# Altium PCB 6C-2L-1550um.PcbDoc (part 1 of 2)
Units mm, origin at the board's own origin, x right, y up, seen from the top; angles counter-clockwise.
Board outline 120.5 x 75.92 mm, 2 copper layers (Top Layer, Bottom Layer), stack 1.586 mm thick; 122 components, 111 nets, 420 pads, 133 vias.
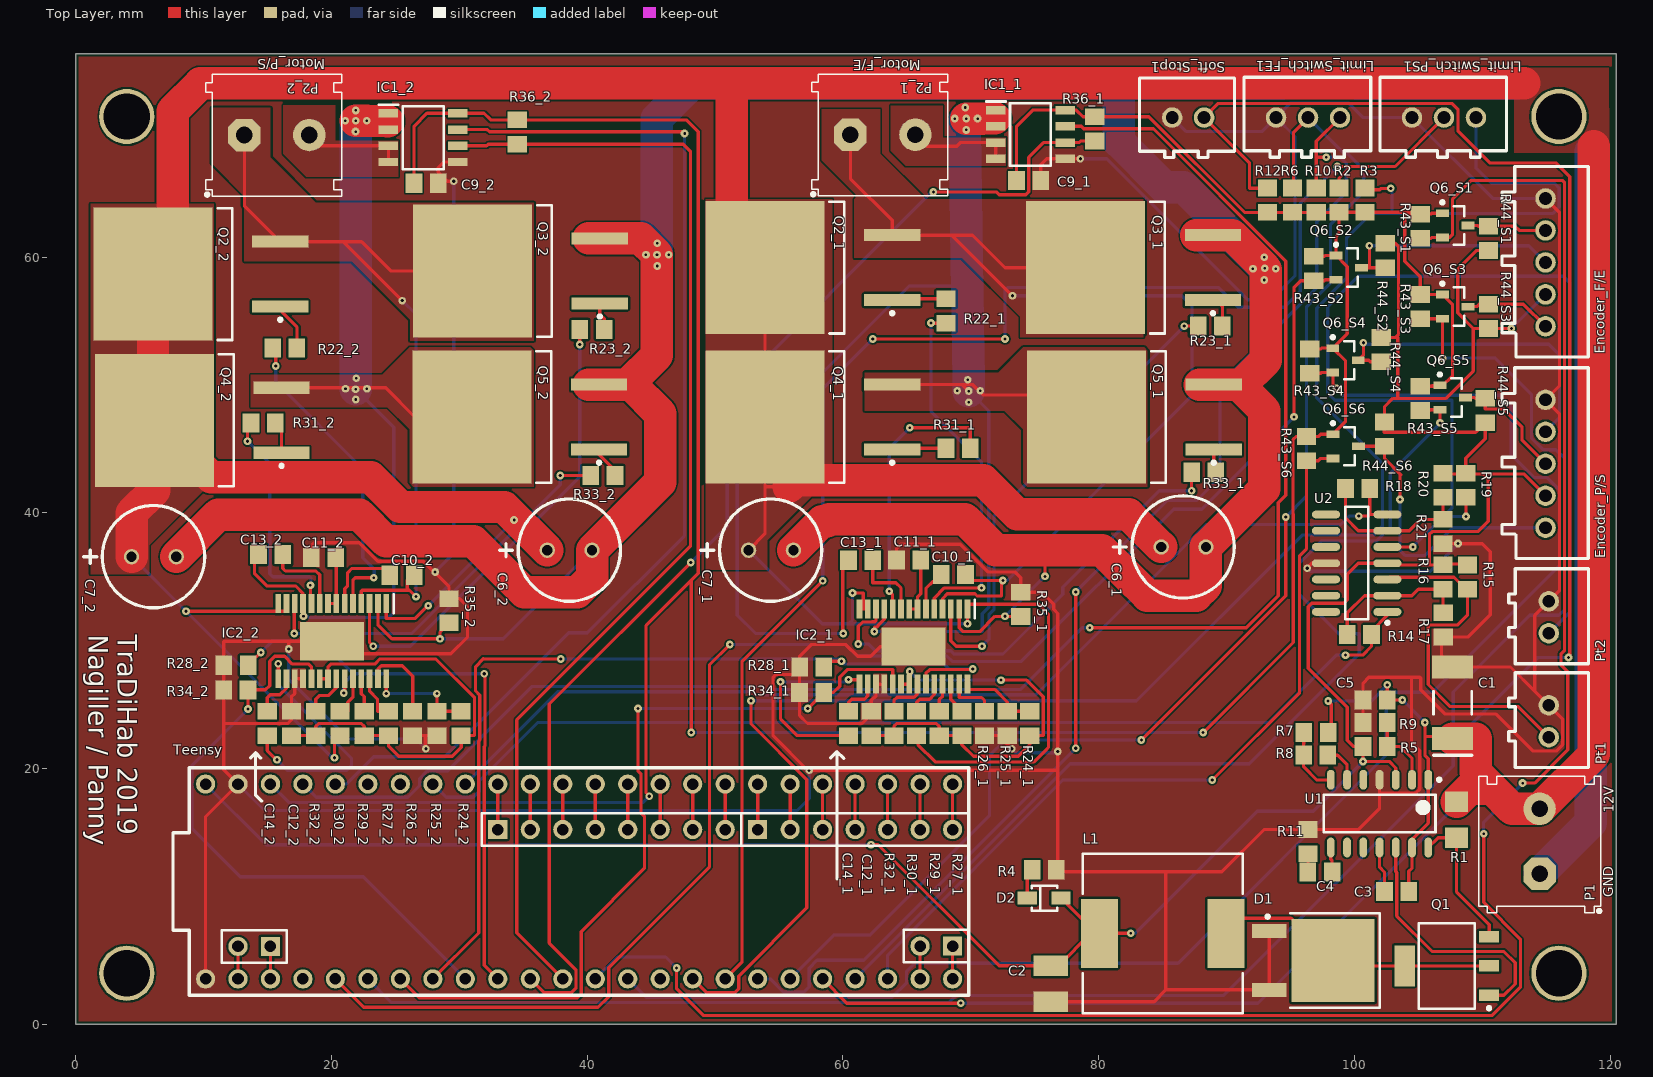
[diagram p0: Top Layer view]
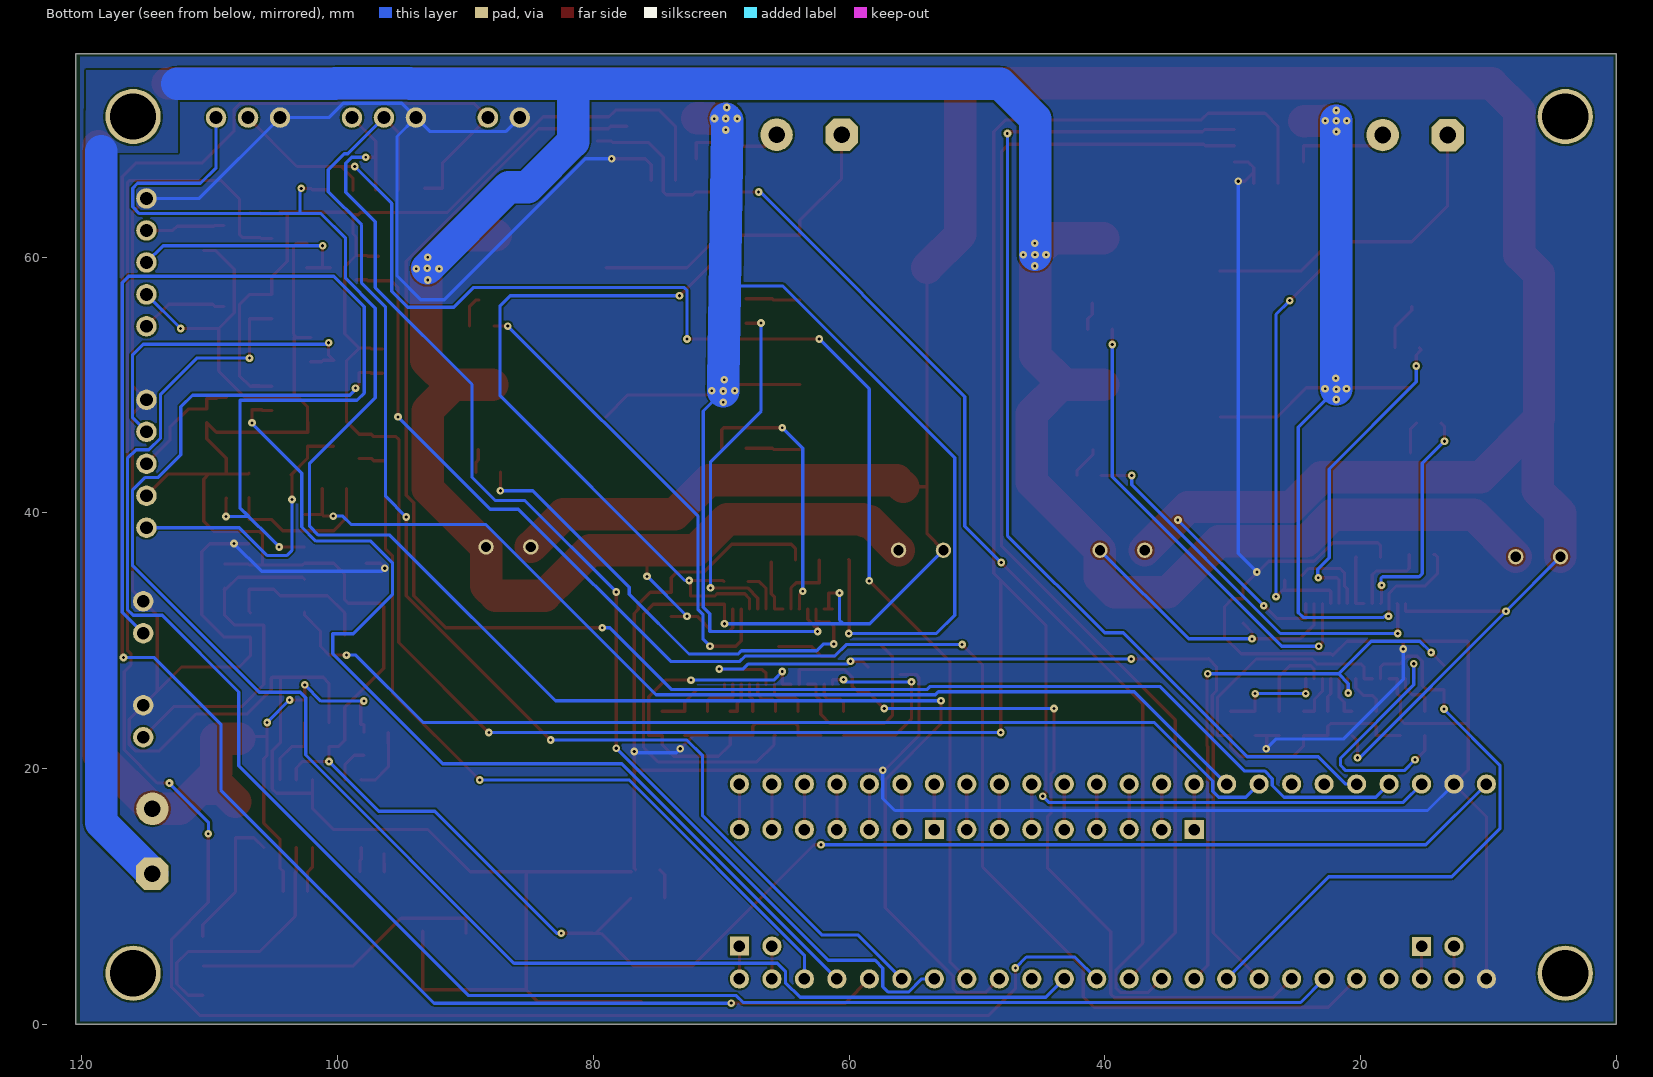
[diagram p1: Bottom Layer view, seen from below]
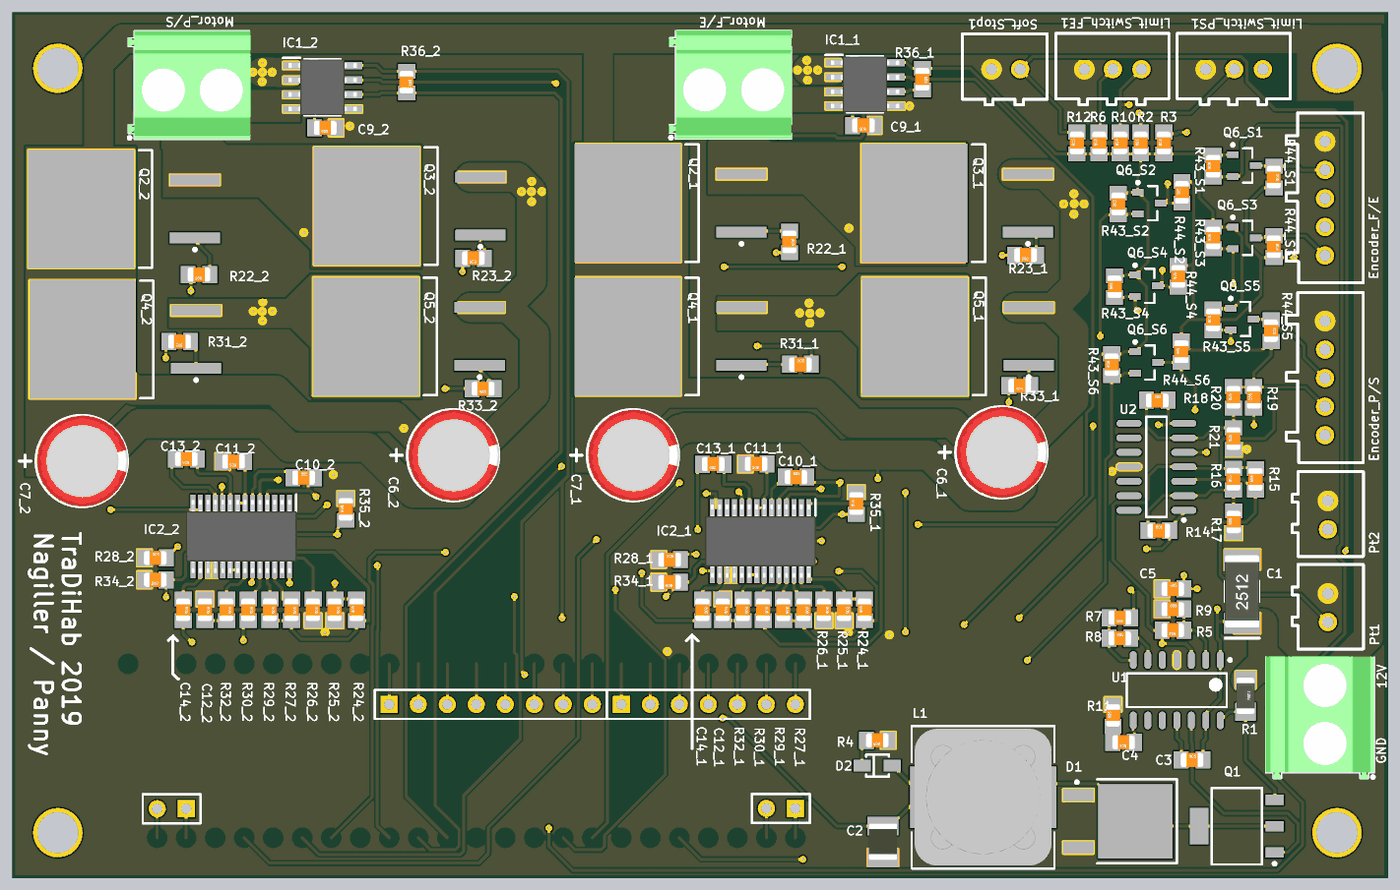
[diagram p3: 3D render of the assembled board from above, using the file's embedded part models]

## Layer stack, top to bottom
Top Solder: solder mask 0.0102, Solder Resist, Dk 3.5
Top Layer: signal copper 0.018
Dielectric1: core 1.55, FR-4, Dk 4.8
Bottom Layer: signal copper 0.018
Bottom Solder: solder mask 0.0102, Solder Resist, Dk 3.5

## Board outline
0,0 120.498,0 120.498,75.921 0,75.921

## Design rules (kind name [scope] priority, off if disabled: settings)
Clearance [All] p1: gap=0.152 ignorepadtopadclearanceinfootprint=FALSE
PolygonConnect PolygonConnect_4 [All vs IsNamedPolygon('Top Layer-No Net') Or  IsNamedPolygon('Top Layer-No Net') Or  IsNamedPolygon('Top Layer-No Net') Or  IsNamedPolygon('Top Layer-No Net') Or  IsNamedPolygon('Top Layer-No Net') Or  IsNamedPolygon('Top Layer-No Net 1') Or  IsNamedPolygon('Top Layer-No Net') Or  IsNamedPolygon('Top Layer-No Net 1') Or  IsNamedPolygon('Top Layer-No Net 1') Or  IsNamedPolygon('Top Layer-No Net 1')] p1: connectstyle=Direct reliefconductorwidth=0.254 reliefentries=4 polygonreliefangle="90 Angle" airgapwidth=0.254
PolygonConnect PolygonConnect_3 [All vs IsNamedPolygon('Top Layer-No Net 1')] p2: connectstyle=Direct reliefconductorwidth=0.254 reliefentries=4 polygonreliefangle="90 Angle" airgapwidth=0.254
PolygonConnect PolygonConnect_2 [All vs IsNamedPolygon('Top Layer-No Net 1')] p3: connectstyle=Direct reliefconductorwidth=0.254 reliefentries=4 polygonreliefangle="90 Angle" airgapwidth=0.254
PolygonConnect PolygonConnect_1 [All vs IsNamedPolygon('Top Layer-No Net 1')] p4: connectstyle=Direct reliefconductorwidth=0.254 reliefentries=4 polygonreliefangle="90 Angle" airgapwidth=0.254
PolygonConnect [All] p5: connectstyle=Direct reliefconductorwidth=0.254 reliefentries=4 polygonreliefangle="90 Angle" airgapwidth=0.254
RoutingVias [All] p1: holewidth=0.25 width=0.6 viastyle="Through Hole" minholewidth=0.2 minwidth=0.25 maxholewidth=0.1 maxwidth=2
SolderMaskExpansion [All] p1: expansion=0.102
Width [All] p1: maxlimit=2.54 minlimit=0.254 preferedwidth=0.254
30 further rules are at their usual default settings.

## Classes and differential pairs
component class 1: C6_1 C7_1 C9_1 C10_1 C11_1 C12_1 C13_1 C14_1 IC1_1 P2_1 Q2_1 Q3_1 Q4_1 Q5_1 R22_1 R23_1 R24_1 R25_1 R26_1 R27_1 R28_1 R29_1 R30_1 R31_1 R32_1 R33_1 R34_1 R35_1 R36_1
component class 2: C6_2 C7_2 C9_2 C10_2 C11_2 C12_2 C13_2 C14_2 IC1_2 IC2_2 P2_2 Q2_2 Q3_2 Q5_2 R22_2 R23_2 R24_2 R25_2 R26_2 R27_2 R28_2 R29_2 R30_2 R31_2 R32_2 R33_2 R34_2 R35_2 R36_2
component class PCB_TraDiHab: C1 C2 C3 C4 C5 D1 D2 Encoder_F/E Encoder_P/S L1 Limit_Switch_FE1 Limit_Switch_PS1 P1 Pt1 Pt2 Q1 R1 R2 R3 R4 R5 R6 R7 R8 R9 R10 R11 R12 R14 R15 R16 R17 R18 R19 R20 R21 Soft_Stop1 Teensy U1 U2
channel class motor: 1 2
component class S1: Q6_S1 R43_S1 R44_S1
component class S2: Q6_S2 R43_S2 R44_S2
component class S3: Q6_S3 R43_S3 R44_S3
component class S4: Q6_S4 R43_S4 R44_S4
component class S5: Q6_S5 R43_S5 R44_S5
component class S6: Q6_S6 R43_S6 R44_S6
channel class Level_shift: S1 S2 S3 S4 S5 S6

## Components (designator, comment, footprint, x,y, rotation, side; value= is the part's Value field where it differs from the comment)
C1 "100µF/25V Tan" C 107.696,25.152 r90 top
C2 "100µF/16V" _1210 76.248,3.178 r90 top
C3 "220nF" _0805 103.312,10.39 r0 top
C4 "22nF" _0805 97.316,11.914 r180 top
C5 "220nF" _0805 101.634,25.376 r0 top
C6_1 "100µF" Cap_THT_Elko_rad_D8mm 86.614,37.338 r0 top (schematic designator C6)
C6_2 "100µF" Cap_THT_Elko_rad_D8mm 38.608,37.084 r0 top (schematic designator C6)
C7_1 "100µF" Cap_THT_Elko_rad_D8mm 54.352,37.084 r0 top (schematic designator C7)
C7_2 "100µF" Cap_THT_Elko_rad_D8mm 6.092,36.576 r0 top (schematic designator C7)
C9_1 "100nF" _0805 74.535,65.989 r180 top (schematic designator C9)
C9_2 "100nF" _0805 27.418,65.786 r180 top (schematic designator C9)
C10_1 "100nF" _0805 68.641,35.179 r0 top (schematic designator C10)
C10_2 "100nF" _0805 25.527,35.128 r0 top (schematic designator C10)
C11_1 "4,7µF" _0805 65.151,36.322 r180 top (schematic designator C11)
C11_2 "4,7µF" _0805 19.39,36.525 r180 top (schematic designator C11)
C12_1 "1µF" _0805 62.224,23.534 r270 top (schematic designator C12)
C12_2 "1µF" _0805 16.881,23.536 r270 top (schematic designator C12)
C13_1 "100nF" _0805 61.392,36.297 r180 top (schematic designator C13)
C13_2 "100nF" _0805 15.255,36.754 r180 top (schematic designator C13)
C14_1 "470nF" _0805 60.452,23.534 r270 top (schematic designator C14)
C14_2 "470nF" _0805 14.986,23.536 r270 top (schematic designator C14)
D1 "IDD03SG60C" TO_252 95,5 r0 top
D2 "yellow" LED_SMD 75.768,9.881 r0 top
Encoder_F/E "JST_5_top" JST_5_TOP 112.456,64.592 r0 top
Encoder_P/S "JST_5_top" JST_5_TOP 112.456,48.844 r0 top
IC1_1 "ACS71240LLCBTR-030B3" SOIC127P600X175-8N 74.676,69.596 r0 top (schematic designator IC1)
IC1_2 "ACS71240LLCBTR-030B3" SOIC127P600X175-8N 27.178,69.342 r0 top (schematic designator IC1)
IC2_1 "A3941KLPTR" SOP65P640X120-29N 65.523,29.549 r270 top (schematic designator IC2)
IC2_2 "A3941KLPTR" SOP65P640X120-29N 20.066,29.972 r270 top (schematic designator IC2)
L1 "IND_47u_3A8" WE_PD_XXL 85.014,7.112 r180 top
Limit_Switch_FE1 "JST_3_top" JST_3_TOP 93.884,74.417 r90 top
Limit_Switch_PS1 "JST_3_top" JST_3_TOP 104.512,74.417 r90 top
P1 "Power_Supply" WRTBL_2P_508 114.702,14.332 r90 top
P2_1 "WRTBL_2P_508" WRTBL_2P_508 63.144,69.367 r0 top (schematic designator P2)
P2_2 "WRTBL_2P_508" WRTBL_2P_508 15.748,69.342 r0 top (schematic designator P2)
P3 "Header 8" HDR1X8 33.02,15.24 r0 top
P4 "Header 7" HDR1X7 53.34,15.24 r0 top
P5 "Header 2" HDR1X2 15.24,6.096 r180 top
P6 "Header 2" HDR1X2 68.58,6.121 r180 top
Pt1 "JST_2_top" JST_2_TOP 120.21,24.96 r0 top
Pt2 "JST_2_top" JST_2_TOP 120.21,33.088 r0 top
Q1 "BSP613P" INF-PG-SOT223_SC-73_N 107.234,4.572 r180 top
Q2_1 "IPB034N06L3 G" INF-PG-TO-263-3-2_A_N 57.658,59.182 r180 top (schematic designator Q2)
Q2_2 "IPB034N06L3 G" INF-PG-TO-263-3-2_A_N 9.802,58.674 r180 top (schematic designator Q2)
Q3_1 "IPB034N06L3 G" INF-PG-TO-263-3-2_A_N 82.744,59.182 r180 top (schematic designator Q3)
Q3_2 "IPB034N06L3 G" INF-PG-TO-263-3-2_A_N 34.798,58.928 r180 top (schematic designator Q3)
Q4_1 "IPB034N06L3 G" INF-PG-TO-263-3-2_A_N 57.658,47.498 r180 top (schematic designator Q4)
Q4_2 "IPB034N06L3 G" INF-PG-TO-263-3-2_A_N 9.906,47.244 r180 top (schematic designator Q4)
Q5_1 "IPB034N06L3 G" INF-PG-TO-263-3-2_A_N 82.804,47.498 r180 top (schematic designator Q5)
Q5_2 "IPB034N06L3 G" INF-PG-TO-263-3-2_A_N 34.738,47.498 r180 top (schematic designator Q5)
Q6_S1 "BSS138" SOT_23 107.888,62.484 r0 top (schematic designator Q6)
Q6_S2 "BSS138" SOT_23 99.568,59.182 r0 top (schematic designator Q6)
Q6_S3 "BSS138" SOT_23 107.888,56.134 r0 top (schematic designator Q6)
Q6_S4 "BSS138" SOT_23 99.314,51.938 r0 top (schematic designator Q6)
Q6_S5 "BSS138" SOT_23 107.696,49.022 r0 top (schematic designator Q6)
Q6_S6 "BSS138" SOT_23 99.33,45.212 r0 top (schematic designator Q6)
R1 "0,047R" _1206 108,16 r270 top
R2 "10k" _0805 98.806,64.465 r90 top
R3 "10k" _0805 100.838,64.465 r90 top
R4 "470R" _0805 75.753,12.09 r180 top
R5 "" _0805 101.634,21.742 r180 top
R6 "10k" _0805 95.174,64.465 r90 top
R7 "" _0805 97.003,22.835 r180 top
R8 "" _0805 96.984,21.058 r0 top
R9 "" _0805 101.634,23.598 r0 top
R10 "10k" _0805 97.028,64.465 r90 top
R11 "430R" _0805 96.388,14.288 r90 top
R12 "10k" _0805 93.218,64.465 r90 top
R14 "6.8k" _0805 100.396,30.48 r0 top
R15 "4.7k" _0805 108.864,34.976 r90 top
R16 "4.7k" _0805 106.934,34.986 r90 top
R17 "100" _0805 106.959,31.242 r90 top
R18 "6.8k" _0805 100.264,41.91 r0 top
R19 "4.7k" _0805 108.712,42.164 r90 top
R20 "4.7k" _0805 106.934,42.164 r90 top
R21 "100" _0805 106.934,38.542 r90 top
R22_1 "47R5" _0805 68.072,55.792 r270 top (schematic designator R22)
R22_2 "47R5" _0805 16.358,52.908 r180 top (schematic designator R22)
R23_1 "47R5" _0805 88.734,54.61 r180 top (schematic designator R23)
R23_2 "47R5" _0805 40.386,54.356 r180 top (schematic designator R23)
R24_1 "47k" _0805 74.625,23.534 r90 top (schematic designator R24)
R24_2 "47k" _0805 30.15,23.536 r90 top (schematic designator R24)
R25_1 "4k7" _0805 72.854,23.534 r270 top (schematic designator R25)
R25_2 "4k7" _0805 28.254,23.536 r270 top (schematic designator R25)
R26_1 "47k" _0805 71.082,23.534 r270 top (schematic designator R26)
R26_2 "47k" _0805 26.359,23.536 r270 top (schematic designator R26)
R27_1 "47k" _0805 69.31,23.534 r270 top (schematic designator R27)
R27_2 "47k" _0805 24.463,23.536 r270 top (schematic designator R27)
R28_1 "47k" _0805 57.57,27.94 r0 top (schematic designator R28)
R28_2 "47k" _0805 12.537,28.092 r0 top (schematic designator R28)
R29_1 "47k" _0805 67.539,23.534 r270 top (schematic designator R29)
R29_2 "47k" _0805 22.568,23.536 r270 top (schematic designator R29)
R30_1 "20k" _0805 65.767,23.534 r270 top (schematic designator R30)
R30_2 "20k" _0805 20.672,23.536 r270 top (schematic designator R30)
R31_1 "47R5" _0805 69.022,45.058 r0 top (schematic designator R31)
R31_2 "47R5" _0805 14.671,47.041 r180 top (schematic designator R31)
R32_1 "47k" _0805 63.995,23.534 r270 top (schematic designator R32)
R32_2 "47k" _0805 18.777,23.536 r270 top (schematic designator R32)
R33_1 "47R5" _0805 88.226,43.18 r180 top (schematic designator R33)
R33_2 "47R5" _0805 41.236,42.926 r180 top (schematic designator R33)
R34_1 "47k" _0805 57.567,25.959 r180 top (schematic designator R34)
R34_2 "47k" _0805 12.534,26.162 r180 top (schematic designator R34)
R35_1 "0R" _0805 73.914,32.854 r90 top (schematic designator R35)
R35_2 "0R" _0805 29.21,32.346 r90 top (schematic designator R35)
R36_1 "" _0805 79.705,70.038 r270 top (schematic designator R36)
R36_2 "" _0805 34.544,69.784 r270 top (schematic designator R36)
R43_S1 "10k" _0805 105.156,62.418 r90 top (schematic designator R43)
R43_S2 "10k" _0805 96.836,59.116 r90 top (schematic designator R43)
R43_S3 "10k" _0805 105.156,56.134 r90 top (schematic designator R43)
R43_S4 "10k" _0805 96.52,51.872 r90 top (schematic designator R43)
R43_S5 "10k" _0805 105.156,48.956 r90 top (schematic designator R43)
R43_S6 "10k" _0805 96.266,45.024 r90 top (schematic designator R43)
R44_S1 "10k" _0805 110.49,61.468 r270 top (schematic designator R44)
R44_S2 "10k" _0805 102.424,60.132 r90 top (schematic designator R44)
R44_S3 "10k" _0805 110.49,55.372 r270 top (schematic designator R44)
R44_S4 "10k" _0805 102.108,52.766 r90 top (schematic designator R44)
R44_S5 "10k" _0805 110.236,48.006 r270 top (schematic designator R44)
R44_S6 "10k" _0805 102.362,46.162 r90 top (schematic designator R44)
Soft_Stop1 "JST_2_top" JST_2_TOP 85.756,75.917 r90 top
Teensy "Teensy3.6_TraDiHab" TEENSY3_6FOOTPRINT 170.18,168.656 r90 top
U1 "IFX80471SK V" INF-PG-DSO-14-1_N 101.976,16.486 r270 top
U2 "LM324" SO_14 100.19,36.068 r180 top

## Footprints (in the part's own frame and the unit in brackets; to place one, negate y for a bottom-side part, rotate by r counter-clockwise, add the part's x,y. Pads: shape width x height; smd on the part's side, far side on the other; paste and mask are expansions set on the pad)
_0805 [mm]
  rect 1.3x1.5 smd: 1(-0.95,0) 2(0.95,0)
  body extent -1,-0.64 1,0.62, height 0.78
_1206 [mm]
  rect 1.6x1.8 smd: 1(-1.4,0) 2(1.4,0)
  body extent -1.6,-0.81 1.6,0.79, height 1
_1210 [mm]
  rect 1.6x2.7 smd: 1(-1.4,0) 2(1.4,0)
  body extent -1.57,-1.24 1.63,1.26, height 1.5
C [mm]
  rect 1.8x3.2 smd: 1(-2.8,0) 2(2.8,0)
  silkscreen extent -4.1,-1.5 0.9,1.5, body extent -3.17,-1.5 3.17,1.5, height 1.6
Cap_THT_Elko_rad_D8mm [mm]
  round 1.2 hole 0.8: 1(-1.718,0) 2(1.782,0)
  silkscreen extent -5.46,-4 4,4, body extent -3.94,-4 4.06,4, height 11.74
HDR1X2 [mm] "Connector; Header; 2 Position"
  rect 1.5x1.5 hole 0.9: 1(0,0)
  round 1.5 hole 0.9: 2(2.54,0)
  silkscreen extent -1.27,-1.27 3.81,1.27, body extent -0.3,-0.29 2.84,0.3, height 7
HDR1X7 [mm] "Connector; Header; 7 Position"
  rect 1.5x1.5 hole 0.9: 1(0,0)
  round 1.5 hole 0.9: 2(2.54,0) 3(5.08,0) 4(7.62,0) 5(10.16,0) 6(12.7,0) 7(15.24,0)
  silkscreen extent -1.27,-1.27 16.51,1.27, body extent -0.3,-0.29 15.54,0.33, height 7
HDR1X8 [mm] "Connector; Header; 8 Position"
  rect 1.5x1.5 hole 0.9: 1(0,0)
  round 1.5 hole 0.9: 2(2.54,0) 3(5.08,0) 4(7.62,0) 5(10.16,0) 6(12.7,0) 7(15.24,0) 8(17.78,0)
  silkscreen extent -1.27,-1.27 19.05,1.27, body extent -0.3,-0.29 18.08,0.3, height 7
INF-PG-DSO-14-1_N [mm]
  oval 1.55x0.6 smd: 1(-2.65,3.81) 2(-2.65,2.54) 3(-2.65,1.27) 4(-2.65,0) 5(-2.65,-1.27) 6(-2.65,-2.54) 7(-2.65,-3.81) 8(2.65,-3.81) 9(2.65,-2.54) 10(2.65,-1.27) 11(2.65,0) 12(2.65,1.27) 13(2.65,2.54) 14(2.65,3.81)
  silkscreen extent -2.77,-4.38 1.47,4.79, body extent -2,-4.38 2,4.38, height 1.75
INF-PG-SOT223_SC-73_N [mm]
  rect 1.6x0.9 smd: 1(-3.3,2.3) 2(-3.3,0) 3(-3.3,-2.3)
  rect 1.6x3.2 smd: 4(3.3,0)
  silkscreen extent -3.43,-3.35 2.2,3.42, body extent -1.85,-3.35 1.85,3.35, height 1.8
INF-PG-TO-263-3-2_A_N [mm]
  rect 4.4x0.95 smd: 1(-6.2,2.54) 3(-6.2,-2.54)
  rect 9.3x10.4 smd: 2(3.75,0)
  silkscreen extent -6.33,-5.15 -1.3,5.15, body extent -2.45,-5.15 7,5.15, height 4.57
JST_2_TOP [mm]
  round 1.6 hole 1: 1(-5,0) 2(-5,-2.5)
  silkscreen extent -8.13,-4.87 -1.9,2.55, body extent -8.25,-5 -1.77,2.68, height 7
JST_3_TOP [mm]
  round 1.6 hole 1: 1(-3.5,0) 2(-3.5,-2.5) 3(-3.5,-5)
  silkscreen extent -6.6,-7.4 -0.35,2.5, body extent -6.73,-7.53 -0.22,2.63, height 7
JST_5_TOP [mm]
  round 1.6 hole 1: 1(2.5,0) 2(2.5,-2.5) 3(2.5,-5) 4(2.5,-7.5) 5(2.5,-10)
  silkscreen extent -0.9,-12.4 5.85,2.5, body extent -1.03,-12.53 5.98,2.63, height 7
LED_SMD [mm]
  rect 1.5x1 smd: 1(1.298,0) 2(-1.349,0)
  silkscreen extent -1,-0.98 1,0.98, body extent -1.12,-0.85 1.23,0.85, height 1.3
SO_14 [mm]
  oval 2.2x0.6 smd: 1(-2.4,3.81) 2(-2.4,2.54) 3(-2.4,1.27) 4(-2.4,0) 5(-2.4,-1.27) 6(-2.4,-2.54) 7(-2.4,-3.81) 8(2.4,-3.81) 9(2.4,-2.54) 10(2.4,-1.27) 11(2.4,0) 12(2.4,1.27) 13(2.4,2.54) 14(2.4,3.81)
  silkscreen extent -2.53,-4.4 0.9,4.78, body extent -2,-4.38 2,4.38, height 1.75
SOIC127P600X175-8N [mm]
  rect 1.525x0.65 smd: 1(-2.712,1.905) 2(-2.712,0.635) 3(-2.712,-0.635) 4(-2.712,-1.905) 5(2.712,-1.905) 6(2.712,-0.635) 7(2.712,0.635) 8(2.712,1.905)
  silkscreen extent -3.48,-2.45 1.6,2.58, body extent -3,-2.45 3,2.45, height 1.75
SOP65P640X120-29N [mm]
  rect 1.475x0.45 smd: 1(-2.938,4.225) 2(-2.938,3.575) 3(-2.938,2.925) 4(-2.938,2.275) 5(-2.938,1.625) 6(-2.938,0.975) 7(-2.938,0.325) 8(-2.938,-0.325) 9(-2.938,-0.975) 10(-2.938,-1.625) 11(-2.938,-2.275) 12(-2.938,-2.925) 13(-2.938,-3.575) 14(-2.938,-4.225) 15(2.938,-4.225) 16(2.938,-3.575) 17(2.938,-2.925) 18(2.938,-2.275) 19(2.938,-1.625) 20(2.938,-0.975) 21(2.938,-0.325) 22(2.938,0.325) 23(2.938,0.975) 24(2.938,1.625) 25(2.938,2.275) 26(2.938,2.925) 27(2.938,3.575) 28(2.938,4.225)
  rect 3x5 smd: 29(0,0)
  silkscreen extent -3.68,4.8 -2.2,4.8, body extent -3.2,-4.85 3.2,4.85, height 1.2
SOT_23 [mm]
  rect 1x0.6 smd: 1(-1,0.95) 2(-1,-0.95) 3(1,0)
  silkscreen extent -1.12,-1.5 0.7,1.92, body extent -0.7,-1.5 0.7,1.5, height 1.1
TEENSY3_6FOOTPRINT [mm]
  round 1.5 hole 0.9: 1(-165.1,160.02) 2(-165.1,157.48) 3(-165.1,154.94) 4(-165.1,152.4) 5(-165.1,149.86) 6(-165.1,147.32) 7(-165.1,144.78) 8(-165.1,142.24) 9(-165.1,139.7) 10(-165.1,137.16) 11(-165.1,134.62) 12(-165.1,132.08) 13(-165.1,129.54) 14(-165.1,127) 15(-165.1,124.46) 16(-165.1,121.92) 17(-165.1,119.38) 18(-165.1,116.84) 19(-165.1,114.3) 20(-165.1,111.76) 21(-165.1,109.22) 22(-165.1,106.68) 23(-165.1,104.14) 24(-165.1,101.6) 25(-149.86,160.02) 26(-149.86,157.48) 27(-149.86,154.94) 28(-149.86,152.4) 29(-149.86,149.86) 30(-149.86,147.32) 31(-149.86,144.78) 32(-149.86,142.24) 33(-149.86,139.7) 34(-149.86,137.16) 35(-149.86,134.62) 36(-149.86,132.08) 37(-149.86,129.54) 38(-149.86,127) 39(-149.86,124.46) 40(-149.86,121.92) 41(-149.86,119.38) 42(-149.86,116.84) 43(-149.86,114.3) 44(-149.86,111.76) 45(-149.86,109.22) 46(-149.86,106.68) 47(-149.86,104.14) 48(-149.86,101.6)
  silkscreen extent -166.37,100.33 -148.59,162.56, body extent -166.5,100.2 -148.46,162.69, height 14
TO_252 [mm]
  rect 2.7x1.1 smd: 1(-1.643,2.3) 2(-1.643,-2.3)
  rect 6.5x6.5 smd: 3(3.346,0)
  silkscreen extent -1.9,-3.68 6.99,3.68, body extent 0,-3.43 6.73,3.43, height 2.3
WE_PD_XXL [mm]
  rect 2.9x5.4 smd: 1(-4.95,0) 2(4.95,0)
  silkscreen extent -6.25,-6.25 6.25,6.25, body extent -6,-6 6,6, height 10.36
WRTBL_2P_508 [mm]
  oct 2.54x2.54 hole 1.3: 1(-2.549,0.212)
  round 2.54 hole 1.3: 2(2.531,0.212)
  silkscreen extent -5.59,-4.57 5.08,4.95, body extent -5.62,-4.55 5.11,4.95, height 15

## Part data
C1: library part Cap_56, Capacity=47u, Voltage=25v
C2: library part Cap_65, Capacity=?F, Voltage=?V
C3 C5: library part Cap_63, Capacity=?F, Voltage=?V
C4 C9_1 C9_2 C10_1 C10_2 C11_1 C11_2 C13_1 C13_2 C14_1 C14_2: library part Cap_129
C6_1 C6_2 C7_1 C7_2: library part Cap_15, Capacity=100u, Voltage=35V
C12_1 C12_2: library part Cap_128
D1: library part DIODE_12, Current / Power="3.5 A"
D2: library part DIODE_60, Colour=blau
IC1_1 IC1_2: library part ACS712ELCTR-20A-T, "Integrated Circuit", Manufacturer_Name="Allegro Microsystems", RS Part Number=6807135P
IC2_1 IC2_2: "Integrated Circuit", Manufacturer_Name="Allegro Microsystems", RS Part Number=7248704P
L1: library part Ind_8, "Inductor", Current="3.8 A", Inductivity="47 uH"
P1 P2_1 P2_2: library part Con_7
P3: library part Con_38
P4: library part Con_37
P5 P6: library part Con_32
Q1: library part Tran_33, "P-Channel SIPMOS Small-Signal-Transistor, -60 V VDS, -2.9 A ID, -55 to 150 degC, PG-SOT223 (SC-73), Reel, Green", Manufacturer=Infineon, Supplier Part Number 1=BSP613P-ND
Q2_1 Q2_2 Q3_1 Q3_2 Q4_1 Q4_2 Q5_1 Q5_2: "N-Channel OptiMOS 3 Power-Transistor, 60 V VDS, 90 A ID, -55 to 175 degC, PG-TO-263-3-2, Reel, Green", Manufacturer=Infineon, Supplier Part Number 1="IPB034N06L3 GTR-ND"
Q6_S1 Q6_S2 Q6_S3 Q6_S4 Q6_S5 Q6_S6: library part Tran_11, Current="2.2 A"
R1: library part Res_7
R2 R3 R6 R10 R12 R14 R15 R16 R17 R18 R19 R20 R21 R36_1 R36_2 R43_S1 R43_S2 R43_S3 R43_S4 R43_S5 R43_S6 R44_S1 R44_S2 R44_S3 R44_S4 R44_S5 R44_S6: library part Res_6
R4 R5 R7 R8 R9 R11 R22_1 R22_2 R23_1 R23_2 R24_1 R24_2 R25_1 R25_2 R26_1 R26_2 R27_1 R27_2 R28_1 R28_2 R29_1 R29_2 R30_1 R30_2 R31_1 R31_2 R32_1 R32_2 R33_1 R33_2 R34_1 R34_2 R35_1 R35_2: library part Res_5
U1: "Step-Down DC/DC Controller, 2,300 mA Iq, -40 to 125 degC, PG-DSO-14-1, Reel, Green", Manufacturer=Infineon, Max Peak Reflow Temp="260 degC", Supplier Part Number 1="IFX80471SK VINTR-ND", Tolerance=3(5)%
U2: library part IC_46

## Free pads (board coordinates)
  round 4.318 hole 3.599: 6(4,4) 6(4,71) 6(116,4) 6(116,71)

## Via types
v1: diameter 0.6, hole 0.25, Top Layer to Bottom Layer, 89 vias
v2: diameter 0.6, hole 0.2, Top Layer to Bottom Layer, 44 vias

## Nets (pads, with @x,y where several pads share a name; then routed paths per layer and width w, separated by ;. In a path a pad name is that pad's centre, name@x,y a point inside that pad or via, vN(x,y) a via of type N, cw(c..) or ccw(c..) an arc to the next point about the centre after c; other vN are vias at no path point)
3V3: C9_1.2 C9_2.2 IC1_1.8 IC1_2.8 Q6_S1.1 Q6_S2.1 Q6_S3.1 Q6_S4.1 Q6_S5.1 Q6_S6.1 R2.1 R3.1 R6.1 R10.1 R12.1 R36_1.1 R36_2.1 R43_S1.2 R43_S2.2 R43_S3.2 R43_S4.2 R43_S5.2 R43_S6.2 Teensy.27 | length 277.1
  Top Layer w0.254: C9_2.2@26.468,65.786 26.468,70.243 27.472,71.247 IC1_2.8@29.89,71.247 31.94,71.247 32.453,70.734 R36_2.1@34.544,70.734 47.757,70.734 48.687,69.804 48.687,35.276 48.145,34.734 ; v1(44.869,17.843) 44.616,18.096 44.616,31.205 48.145,34.734 ; v1(48.145,22.821) 48.145,34.734 ; C9_1.2@73.585,65.989 73.585,70.243 74.843,71.501 IC1_1.8@77.388,71.501 78.27,71.501 78.783,70.988 R36_1.1@79.705,70.988 83.924,70.988 91.412,63.5 98.191,63.5 98.379,63.312 R2.1@98.806,63.312 ; v1(88.176,22.821) 95.22,29.866 95.22,39.915 95.211,39.923 95.211,45.745 95.44,45.974 R43_S6.2@96.266,45.974 97.193,45.974 97.381,46.162 Q6_S6.1@98.33,46.162 99.321,47.153 99.321,51.881 Q6_S4.1@98.314,52.888 ; R43_S4.2@96.52,52.822 97.37,52.822 97.436,52.888 Q6_S4.1@98.314,52.888 ; R43_S2.2@96.836,60.066 97.65,60.066 97.716,60.132 Q6_S2.1@98.568,60.132 ; Q6_S5.1@106.696,49.972 106.078,49.972 R43_S5.2@105.156,49.906 106.853,49.906 107.683,50.736 107.683,56.289 Q6_S3.1@106.888,57.084 R43_S3.2@105.156,57.084 105.156,58.458 103.937,59.677 103.937,63.515 ; Q6_S1.1@106.888,63.434 106.047,63.434 105.981,63.368 R43_S1.2@105.156,63.368 104.338,63.368 104.485,63.515 103.937,63.515 ; Q6_S4.1@98.314,52.888 99.453,54.027 99.453,59.247 Q6_S2.1@98.568,60.132 ; Q6_S2.1@98.568,60.132 98.568,61.582 98.806,61.82 R2.1@98.806,63.312 ; R2.1@98.806,63.312 99.009,63.515 R3.1@100.838,63.515 103.937,63.515
  Bottom Layer w0.254: Teensy.27@15.24,18.796 16.676,17.36 44.386,17.36 v1(44.869,17.843) ; v1(48.145,22.821) v1(88.176,22.821)
5V: C2.2 D2.1 Encoder_F/E.4 Encoder_P/S.4 L1.2 R5.2 R15.2 R16.2 R19.2 R20.2 R44_S1.2 R44_S2.2 R44_S3.2 R44_S4.2 R44_S5.2 R44_S6.2 Teensy.25 U1.3 U2.4 | length 216
  Top Layer w0.254: v1(62.205,14.046) 62.751,14.046 72.219,4.578 C2.2@76.248,4.578 76.873,4.578 79.407,7.112 L1.2@80.064,7.112 ; D2.1@77.067,9.881 79.835,7.112 L1.2@80.064,7.112 ; v2(82.525,7.137) 80.089,7.137 L1.2@80.064,7.112 ; R44_S4.2@102.108,53.716 103.195,53.716 ; R44_S2.2@102.424,61.082 103.191,61.082 103.466,60.807 103.466,53.987 103.195,53.716 ; U1.3@103.246,19.136 103.246,20.053 102.733,20.565 v1(100.684,20.565) R5.2@100.684,21.742 99.91,21.742 99.44,22.213 99.44,24.816 96.405,27.851 96.405,32.677 96.659,32.931 99.174,32.931 99.479,33.235 99.479,35.23 100.317,36.068 U2.4@102.59,36.068 102.722,35.936 105.879,35.936 ; R20.2@106.934,43.114 107,43.048 R19.2@108.712,43.048 ; R15.2@108.859,36.002 107,36.002 R16.2@106.934,35.936 105.879,35.936 ; R44_S1.2@110.49,60.518 109.537,60.518 108.089,59.07 108.089,55.641 109.308,54.422 ; v1(112.286,54.422) R44_S3.2@110.49,54.422 109.308,54.422 ; Encoder_P/S.4@114.956,41.344 113.252,43.048 110.07,43.048 ; 103.195,53.716 103.403,53.716 103.403,48.958 ; 103.403,48.958 107.175,48.958 109.308,51.092 109.308,54.422 ; 103.403,48.958 103.022,48.958 102.362,48.298 R44_S6.2@102.362,47.112 102.349,47.112 102.349,46.304 109.484,46.304 R44_S5.2@110.236,47.056 110.236,45.808 108.712,44.284 R19.2@108.712,43.048 ; 105.879,35.936 105.879,38.341 106.083,38.544 109.664,38.544 110.477,39.357 110.477,42.642 110.07,43.048 ; R19.2@108.712,43.048 110.07,43.048
  Bottom Layer w0.254: Teensy.25@10.16,18.796 14.91,14.046 v1(62.205,14.046) ; v2(82.525,7.137) 82.88,7.137 92.405,16.662 96.781,16.662 v1(100.684,20.565) ; v1(112.286,54.422) Encoder_F/E.4@114.956,57.092
5V_1: C12_1.2 IC2_1.20 IC2_1.21 R24_1.1 R27_1.2 R29_1.2 R32_1.2 | length 33.2
  Top Layer w0.254: C12_1.2@62.224,22.584 R32_1.2@63.995,22.584 63.995,23.304 64.224,23.533 67.31,23.533 67.539,23.304 R29_1.2@67.539,22.584 R27_1.2@69.31,22.584 69.31,21.882 70.22,20.972 73.716,20.972 74.625,21.882 R24_1.1@74.625,22.584 75.679,22.584 75.679,25.616 74.371,26.924 v1(72.365,26.924) ; IC2_1.20@64.548,26.611 IC2_1.21@65.198,26.611 65.232,26.644 v2(65.232,27.596) v2@65.215,27.596
  Bottom Layer w0.254: v2(65.232,27.596) 65.904,26.924 v1(72.365,26.924)
5V_2: C12_2.2 IC2_2.20 IC2_2.21 R24_2.1 R27_2.2 R29_2.2 R32_2.2 | length 35.8
  Top Layer w0.254: C12_2.2@16.881,22.586 R32_2.2@18.777,22.586 18.777,23.304 19.006,23.533 22.339,23.533 22.568,23.304 R29_2.2@22.568,22.586 R27_2.2@24.463,22.586 24.463,21.789 25.28,20.972 29.456,20.972 30.15,21.666 R24_2.1@30.15,22.586 31.203,22.586 31.203,25.539 28.165,28.577 23.785,28.577 23.389,28.181 19.944,28.181 19.741,27.978 IC2_2.21@19.741,27.034 IC2_2.20@19.091,27.034
GND: C1.2 C2.1 C5.1 C9_1.1 C9_2.1 C11_1.2 C11_2.2 C12_1.1 C12_2.1 D1.1 D1.2 Encoder_F/E.1 Encoder_P/S.1 IC1_1.5 IC1_2.5 IC2_1.17 IC2_1.18 IC2_1.29 IC2_2.17 IC2_2.18 IC2_2.29 Limit_Switch_FE1.1 Limit_Switch_PS1.1 Pt1.1 Pt2.1 R4.1 R9.1 R11.2 R17.1 R21.1 R25_1.2 R25_2.2 R26_1.2 R26_2.2 R28_1.1 R28_2.1 R34_1.2 R34_2.2 R35_1.2 R35_2.2 Soft_Stop1.1 Teensy.1 Teensy.26 U1.4 U2.11 | length 527.4
  Top Layer w0.254: Teensy.1@10.16,3.556 10.16,16.256 Teensy.26@12.7,18.796 11.584,19.912 11.584,23.544 ; v1(16.662,29.362) 16.662,29.896 16.586,29.972 ; IC2_2.18@17.791,27.034 IC2_2.17@17.141,27.034 17.141,25.875 16.881,25.615 C12_2.1@16.881,24.486 16.881,23.816 16.598,23.533 11.596,23.533 11.584,23.544 ; C11_2.2@18.44,36.525 18.44,37.44 18.669,37.668 22.195,37.668 23.643,36.22 27.203,36.22 29.21,34.214 R35_2.2@29.21,33.296 30.025,33.296 30.646,32.675 30.646,30.29 29.34,28.984 22.311,28.984 22.184,28.857 21.069,29.972 IC2_2.29@20.066,29.972 16.586,29.972 ; R26_2.2@26.359,22.586 27.343,22.586 ; v1(27.393,21.551) 27.343,21.602 27.343,22.586 ; R25_2.2@28.254,22.586 27.343,22.586 ; C9_2.1@28.368,65.786 28.368,66.627 ; v1(29.566,65.938) 29.057,65.938 28.368,66.627 ; IC1_2.5@29.89,67.437 28.79,67.437 28.368,67.015 28.368,66.627 ; R28_1.1@56.019,27.368 54.749,27.368 54.546,27.165 54.546,22.567 57.238,19.875 v1(57.365,19.875) 76.746,19.875 76.81,19.939 ; IC2_1.18@63.248,26.611 IC2_1.17@62.598,26.611 62.598,25.711 62.224,25.336 C12_1.1@62.224,24.484 62.224,24.251 61.506,23.533 57.238,23.533 56.617,24.154 R34_1.2@56.617,25.959 56.617,26.936 56.62,26.94 R28_1.1@56.62,27.94 56.62,28.798 57.526,29.705 60.239,29.705 61.154,28.79 62.17,28.79 62.928,29.549 IC2_1.29@65.523,29.549 ; C11_1.2@64.201,36.322 64.201,37.226 64.516,37.541 69.19,37.541 71.349,35.382 73.457,35.382 73.914,34.925 R35_1.2@73.914,33.804 75.542,33.804 76.492,32.854 76.492,32.461 ; R26_1.2@71.082,22.584 R25_1.2@72.182,22.584 ; R25_1.2@72.854,22.584 R25_1.2@72.182,22.584 ; v1(73.215,21.551) R25_1.2@72.182,22.584 ; C9_1.1@75.485,65.989 75.485,67.244 75.933,67.691 IC1_1.5@77.388,67.691 v1(78.577,67.691) ; C2.1@76.248,1.778 84.34,1.778 85.262,2.7 ; 76.492,32.451 76.81,32.133 v1(76.81,21.336) 76.81,19.939 ; R4.1@76.703,12.09 76.81,12.197 76.81,19.939 ; R4.1@77.032,11.938 85.192,11.938 ; D1.1@93.357,7.3 D1.2@93.357,2.7 85.262,2.7 ; v1(96.314,35.674) 96.314,35.723 96.659,36.068 U2.11@97.79,36.068 ; R9.1@100.684,23.598 C5.1@100.684,25.376 100.684,26.694 101.13,27.139 104.394,27.139 ; U1.4@101.976,19.136 101.976,18.072 ; R21.1@106.934,37.592 v1@108.102,37.592 ; v1(108.115,37.604) v1@108.102,37.592 ; Encoder_F/E.1@114.956,64.592 116.039,63.509 116.039,49.927 Encoder_P/S.1@114.956,48.844 116.039,47.761 116.039,33.917 Pt2.1@115.21,33.088 114.109,31.987 114.109,26.061 ; 11.584,23.544 R34_2.2@11.584,26.162 11.584,27.114 11.587,27.117 R28_2.1@11.587,28.092 11.587,29.933 11.626,29.972 16.586,29.972 ; 85.192,11.938 85.262,11.867 85.262,2.7 ; 85.192,11.938 89.637,11.938 92.937,15.238 R11.2@96.388,15.238 100.311,15.238 101.976,16.903 101.976,18.072 ; 101.976,18.072 104.787,18.072 105.117,18.402 105.117,21.399 104.482,22.034 104.482,27.051 104.394,27.139 ; 104.394,27.139 105.144,27.139 105.207,27.076 105.207,26.162 107.1,24.269 111.086,24.269 113.982,21.374 115.785,21.374 116.293,21.882 116.293,23.877 Pt1.1@115.21,24.96 114.109,26.061 ; v1@108.102,37.592 110.007,37.592 110.629,36.97 110.629,32.042 108.88,30.292 106.827,30.292 106.827,28.821 C1.2@107.696,27.952 112.218,27.952 114.109,26.061
  Bottom Layer w0.254: Teensy.26@12.7,18.796 14.771,16.725 56.426,16.725 57.365,17.665 v1(57.365,19.875) ; v1(16.662,29.362) 16.662,27 21.349,22.313 26.631,22.313 v1(27.393,21.551) ; v1(28.118,35.382) 29.566,36.83 v1(29.566,65.938) ; v1(73.215,21.551) 73.52,21.247 76.72,21.247 v1(76.81,21.336) ; v1(78.577,67.691) 80.644,67.691 91.655,56.68 93.497,56.68 95.364,58.546 95.364,69.437 Limit_Switch_FE1.1@93.884,70.917 ; Soft_Stop1.1@85.756,70.917 86.836,69.837 92.804,69.837 Limit_Switch_FE1.1@93.884,70.917 ; v1(96.314,35.674) 96.555,35.433 105.943,35.433 v1(108.115,37.604) ; Encoder_F/E.1@114.956,64.592 110.836,64.592 Limit_Switch_PS1.1@104.512,70.917 100.686,70.917 99.568,72.034 95.001,72.034 Limit_Switch_FE1.1@93.884,70.917
NetC3_1: C3.1 U1.11 | length 3.6
  Top Layer w0.254: U1.11@101.976,13.836 101.976,12.285 102.362,11.899 C3.1@102.362,10.39
NetC4_1: C4.1 U1.8 | length 2
  Top Layer w0.254: U1.8@98.166,13.836 98.166,12.914 98.266,12.814 C4.1@98.266,11.914
NetC4_2: C4.2 R11.1 | length 1.4
  Top Layer w0.254: C4.2@96.366,11.914 96.366,12.611 96.388,12.633 R11.1@96.388,13.338
NetC10_1_1: C10_1.1 IC2_1.6 | length 3.2
  Top Layer w0.254: IC2_1.6@66.498,32.487 66.498,34.088 67.056,34.646 C10_1.1@67.899,34.646
NetC10_1_2: C10_1.2 IC2_1.4 P2_1.1 Q2_1.3 Q3_1.2 | length 83.9
  Top Layer w0.254: P2_1.1@60.595,69.579 60.595,66.151 63.858,62.888 Q2_1.3@63.858,61.722 68.528,61.722 ; IC2_1.4@67.798,32.487 67.798,33.305 68.174,33.68 70.318,33.68 70.496,33.503 72.415,33.503 72.415,34.615 v1(72.517,34.717) 69.871,34.717 C10_1.2@69.799,34.646 ; v1(73.266,56.984) 68.528,61.722 ; Q3_1.2@78.994,59.182 72.682,59.182 70.142,61.722 68.528,61.722
  Bottom Layer w0.254: v1(72.517,34.717) 72.842,34.717 87.312,49.187 87.312,56.172 86.499,56.984 v1(73.266,56.984)
NetC10_2_1: C10_2.1 IC2_2.6 | length 6.2
  Top Layer w0.254: IC2_2.6@21.041,32.91 21.041,34.085 21.27,34.313 21.27,35.316 21.615,35.662 24.044,35.662 C10_2.1@24.577,35.128
NetC10_2_2: C10_2.2 IC2_2.4 P2_2.1 Q2_2.3 Q3_2.2 | length 61.9
  Top Layer w0.254: P2_2.1@13.199,69.554 13.199,64.017 Q2_2.3@16.002,61.214 20.929,61.214 ; IC2_2.4@22.341,32.91 22.341,33.886 22.415,33.96 25.932,33.96 ; v1(25.539,56.603) 20.929,61.214 ; C10_2.2@25.932,34.743 25.932,33.96 ; v1(26.619,33.452) 26.111,33.96 25.932,33.96 ; Q3_2.2@31.048,58.928 24.65,58.928 22.364,61.214 20.929,61.214
  Bottom Layer w0.254: v1(25.539,56.603) 26.619,55.523 v1(26.619,33.452)
NetC11_1_1: C11_1.1 IC2_1.7 IC2_1.8 | length 4.4
  Top Layer w0.254: IC2_1.8@65.198,32.487 IC2_1.7@65.848,32.487 65.848,33.439 66.086,33.676 C11_1.1@66.086,36.144
NetC11_2_1: C11_2.1 IC2_2.7 IC2_2.8 | length 4.3
  Top Layer w0.254: IC2_2.8@19.741,32.91 IC2_2.7@20.391,32.91 20.391,36.535 C11_2.1@20.34,36.525
NetC13_1_1: C13_1.1 IC2_1.9 | length 5.8
  Top Layer w0.254: C13_1.1@62.342,36.297 62.342,34.534 64.145,34.534 64.548,34.131 IC2_1.9@64.548,32.487
NetC13_1_2: C13_1.2 IC1_1.1 IC1_1.2 IC2_1.11 Q4_1.3 Q5_1.2 | length 146
  Top Layer w0.254: v1(60.032,30.568) 60,30.601 60,36.315 C13_1.2@60.032,36.347 ; v1(62.471,30.721) 62.471,31.076 62.69,31.076 62.744,31.131 62.744,31.164 63.248,31.669 IC2_1.11@63.248,32.487 ; Q4_1.3@63.858,50.038 69.342,50.038 ; v2(69.85,49.53) 69.342,50.038 ; 69.85,70.231 IC1_1.2@71.964,70.231 ; 71.882,70.866 71.882,70.853 71.539,70.853 71.539,70.857 71.539,71.501 IC1_1.1@71.964,71.501 ; Q5_1.2@79.054,47.498 77.327,49.225 70.98,49.225 70.167,50.038 69.342,50.038
  Top Layer w2.54: v2(69.647,70.841) v2(70.536,70.841) 70.917,70.841 71.539,70.857 71.882,70.866
  Bottom Layer w0.254: v1(60.032,30.568) 53.174,30.568 51.752,31.991 51.752,44.31 65.189,57.746 69.254,57.746 69.729,57.271 69.85,57.15 ; v1(62.471,30.721) 70.904,30.721 70.904,32.105 71.42,32.622 71.42,34.378 71.412,34.386 71.412,47.968 v2(69.85,49.53) 69.85,57.15 ; 69.85,70.231 69.85,57.15
  Bottom Layer w2.54: v2(69.647,70.841) 69.52,70.71 69.532,69.95 69.729,57.271 69.836,50.42 69.849,49.569 69.85,49.542 v2(69.85,49.53)
  other v2: 69.85,48.666 68.961,49.555 70.739,49.555 69.774,50.419 69.647,69.952 68.758,70.841 69.571,71.704
NetC13_2_1: C13_2.1 IC2_2.9 | length 6.4
  Top Layer w0.254: C13_2.1@16.205,36.754 16.205,35.662 16.408,35.458 18.796,35.458 19.091,35.163 IC2_2.9@19.091,32.91
NetC13_2_2: C13_2.2 IC1_2.1 IC1_2.2 IC2_2.11 Q4_2.3 Q5_2.2 | length 77.4
  Top Layer w0.254: C13_2.2@14.305,36.754 14.19,36.764 13.995,36.569 13.995,35.23 14.935,34.29 17.196,34.29 17.791,33.695 IC2_2.11@17.791,32.91 17.791,31.971 17.831,31.931 v2(17.824,31.924) ; Q4_2.3@16.106,49.784 v2@21.793,49.784 ; v2(21.895,49.682) v2@21.793,49.784 ; v2@21.895,69.977 IC1_2.2@24.466,69.977 ; 24.409,70.637 24.409,70.65 24.041,70.65 24.041,71.247 IC1_2.1@24.466,71.247 ; Q5_2.2@30.988,47.498 26.543,47.498 24.257,49.784 v2@21.793,49.784
  Top Layer w2.54: v2@21.895,70.663 v2@21.902,70.663 ; v2@21.903,70.663 v2@21.913,70.663 ; v2@21.913,70.663 v2(21.92,70.663) 22.758,70.655 24.383,70.641 24.409,70.637
  Bottom Layer w0.254: v2(17.824,31.924) 18.114,31.924 18.212,31.826 24.485,31.826 24.83,32.172 24.879,32.172 24.879,46.698 v2(21.895,49.682) ; v2(21.895,69.825) v2@21.895,69.977
  Bottom Layer w2.54: v2(21.895,49.682) v2(21.895,69.825) ; v2@21.895,69.977 v2@21.895,70.663
  other v2: 21.92,48.87 21.107,49.708 22.784,49.708 21.946,50.521 21.082,70.663 22.758,70.663 21.92,71.476
NetC14_1_1: C14_1.1 IC2_1.16 | length 3.3
  Top Layer w0.254: C14_1.1@60.452,24.484 60.452,25.197 60.693,25.438 61.694,25.438 61.948,25.692 IC2_1.16@61.948,26.611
